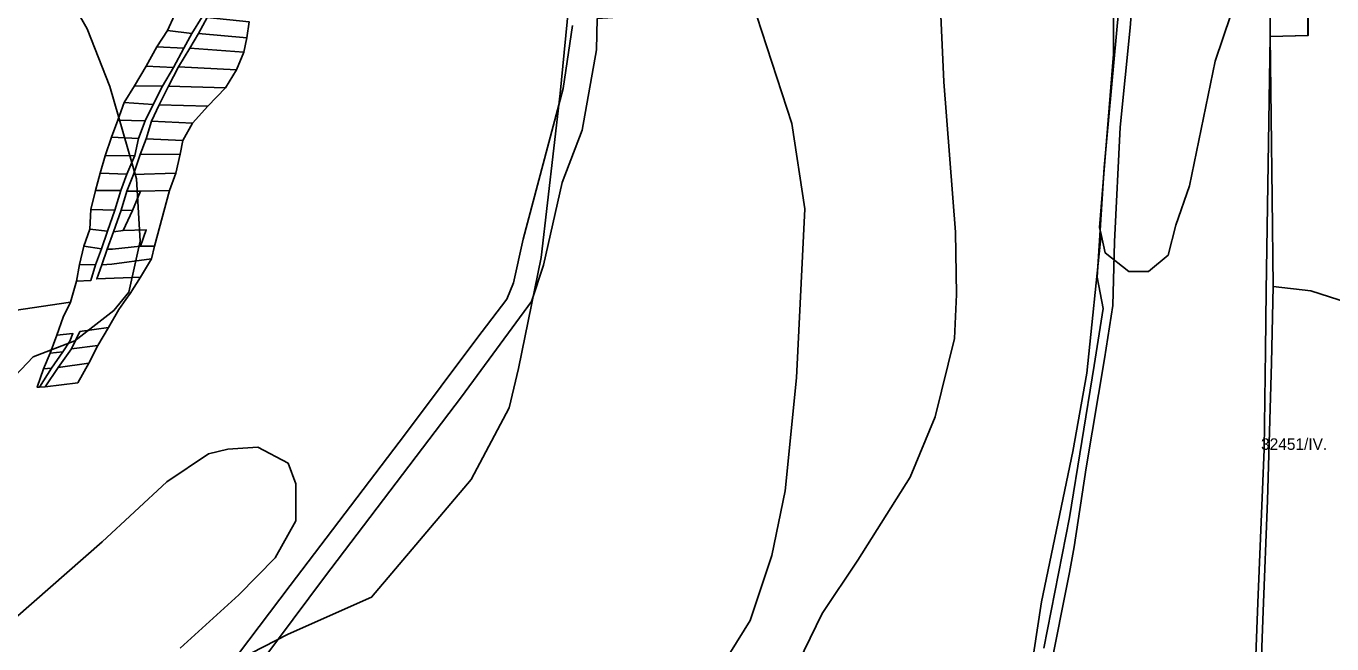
# Model space of a CAD drawing. Extents: x -532083 to -529270, y -1180561 to -1176456.
# Drawn here: x -530773 to -530208, y -1178980 to -1178713 of the extents above; entities that cross this region are included whole.
import ezdxf

# ---------------------------------------------------------------- set-up
doc = ezdxf.new("R2010")
doc.units = 0
for name, color, linetype in [('95560013', 7, 'Continuous'), ('95590013', 7, 'Continuous'), ('95600013', 7, 'Continuous'), ('95610013', 7, 'Continuous'), ('95660013', 7, 'Continuous')]:
    doc.layers.add(name, color=color, linetype=linetype)

msp = doc.modelspace()

# ---------------------------------------------------------------- linework, layer by layer
at = {"layer": '95560013'}
for points in [[(-530173.3683, -1178841.37945), (-530216.8993, -1178827.43745), (-530233.1583, -1178825.59545), (-530233.6833, -1178787.18845), (-530234.4203, -1178717.34745), (-530218.0513, -1178716.96145), (-530218.0513, -1178672.33445), (-530216.3173, -1178635.62945), (-530212.6243, -1178588.41745), (-530208.2113, -1178542.10845), (-530205.6693, -1178522.00845)], [(-530338.6833, -1179036.85645), (-530321.3203, -1178949.31245), (-530319.2753, -1178938.12245), (-530314.0693, -1178903.98945), (-530306.0673, -1178856.85845), (-530302.5943, -1178833.81345), (-530301.7933, -1178806.21445), (-530299.3893, -1178756.64145), (-530295.0563, -1178713.57145), (-530294.2473, -1178704.37145), (-530292.2243, -1178658.50245), (-530281.8383, -1178658.50245), (-530273.2063, -1178658.63745), (-530233.1463, -1178659.44945), (-530234.6123, -1178693.97245), (-530234.4203, -1178717.34745), (-530236.1723, -1178827.37845), (-530236.4583, -1178853.31145), (-530237.1233, -1178896.00145), (-530239.7833, -1178962.37045), (-530242.1383, -1179023.22645)], [(-530690.5463, -1179014.35945), (-530643.5763, -1178951.29245), (-530584.3203, -1178873.36445), (-530554.0423, -1178832.09445), (-530548.8193, -1178816.37645), (-530540.7243, -1178780.48645), (-530532.1063, -1178757.95845), (-530525.8393, -1178723.11645), (-530525.5283, -1178709.61545), (-530477.7553, -1178706.53545), (-530436.3133, -1178704.03345), (-530438.9993, -1178686.51945), (-530406.4623, -1178682.39745), (-530405.3293, -1178687.32245), (-530368.5043, -1178694.52145), (-530341.5003, -1178699.06845), (-530299.9553, -1178705.13045), (-530306.2123, -1178774.10145), (-530309.2763, -1178821.52745), (-530306.6503, -1178835.14045), (-530310.5893, -1178859.73145), (-530321.3073, -1178925.52945), (-530332.4003, -1178981.99545)], [(-530829.5283, -1178843.57645), (-530753.4283, -1178832.35745), (-530756.5093, -1178838.87745), (-530759.3103, -1178846.60445), (-530762.2283, -1178854.44745), (-530765.0293, -1178861.12145), (-530767.8303, -1178869.08245), (-530766.7803, -1178869.08245), (-530764.3293, -1178868.96545), (-530750.2063, -1178867.20945), (-530745.4213, -1178858.77945), (-530741.5703, -1178851.05245), (-530736.9013, -1178843.32545), (-530732.4663, -1178835.48145), (-530729.4203, -1178831.18945), (-530727.5643, -1178828.57445), (-530723.0553, -1178821.56445), (-530718.2813, -1178813.61845), (-530717.0633, -1178808.11745), (-530710.5633, -1178784.07545), (-530707.8203, -1178776.56845), (-530705.9153, -1178768.32545), (-530704.7243, -1178762.35245), (-530700.6753, -1178754.82645), (-530694.0053, -1178747.54045), (-530686.3833, -1178739.65545), (-530681.5013, -1178731.77145), (-530678.3583, -1178724.17245), (-530677.1223, -1178717.97145), (-530676.1083, -1178710.96645)], [(-530536.1813, -1178712.61545), (-530540.2403, -1178739.94945), (-530557.6323, -1178805.08445), (-530561.6903, -1178823.98545), (-530564.5883, -1178830.96445), (-530577.5853, -1178848.02145), (-530608.4863, -1178889.23145), (-530658.2913, -1178954.87545), (-530725.8063, -1179044.23145)]]:
    msp.add_lwpolyline(points, dxfattribs=at)
for points in [[(-530717.0633, -1178808.11745), (-530723.1563, -1178808.11745), (-530720.6173, -1178801.08845), (-530730.5703, -1178801.39345), (-530726.6093, -1178792.63345), (-530723.0553, -1178784.27945), (-530710.5633, -1178784.07545)], [(-530718.2813, -1178813.61845), (-530735.4453, -1178815.85945), (-530739.8123, -1178816.16545), (-530737.5783, -1178809.33945), (-530735.2423, -1178809.33945), (-530723.1563, -1178808.11745), (-530717.0633, -1178808.11745)], [(-530750.2063, -1178867.20945), (-530764.3293, -1178868.96545), (-530758.7273, -1178860.65245), (-530745.4213, -1178858.77945)], [(-530766.7803, -1178869.08245), (-530767.8303, -1178869.08245), (-530765.0293, -1178861.12145), (-530761.5283, -1178860.88745)]]:
    msp.add_lwpolyline(points, close=True, dxfattribs=at)
at = {"layer": '95590013'}
for points in [[(-530700.8893, -1178716.05045), (-530711.4773, -1178714.80745), (-530708.3233, -1178708.14145), (-530696.3843, -1178708.93245)], [(-530677.1223, -1178717.97145), (-530698.0733, -1178716.05045), (-530694.2433, -1178709.15845), (-530676.1083, -1178710.96645)], [(-530704.3813, -1178722.37745), (-530715.9833, -1178721.81245), (-530711.4773, -1178714.80745), (-530700.8893, -1178716.05045)], [(-530678.3583, -1178724.17245), (-530701.8203, -1178722.37545), (-530698.0733, -1178716.05045), (-530677.1223, -1178717.97145)], [(-530708.8873, -1178730.85145), (-530720.7143, -1178730.17345), (-530715.9833, -1178721.81245), (-530704.3813, -1178722.37745)], [(-530681.5013, -1178731.77145), (-530706.6293, -1178730.57645), (-530701.8203, -1178722.37545), (-530678.3583, -1178724.17245)], [(-530713.5373, -1178738.81945), (-530725.7083, -1178738.78045), (-530720.7143, -1178730.17345), (-530708.8873, -1178730.85145)], [(-530686.3833, -1178739.65545), (-530711.0363, -1178738.81945), (-530706.6293, -1178730.57645), (-530681.5013, -1178731.77145)], [(-530717.5863, -1178746.82345), (-530730.1623, -1178745.99845), (-530725.7083, -1178738.78045), (-530713.5373, -1178738.81945)], [(-530694.0053, -1178747.54045), (-530715.0853, -1178746.94245), (-530711.0363, -1178738.81945), (-530686.3833, -1178739.65545)], [(-530721.0403, -1178753.87145), (-530732.9033, -1178753.56045), (-530730.1623, -1178745.99845), (-530717.5863, -1178746.82345)], [(-530700.6753, -1178754.82645), (-530718.3003, -1178753.99045), (-530715.0853, -1178746.94245), (-530694.0053, -1178747.54045)], [(-530723.8983, -1178761.51645), (-530735.6443, -1178760.94945), (-530732.9033, -1178753.56045), (-530721.0403, -1178753.87145)], [(-530704.7243, -1178762.35245), (-530720.6823, -1178761.63645), (-530718.3003, -1178753.99045), (-530700.6753, -1178754.82645)], [(-530725.5653, -1178768.80345), (-530738.3863, -1178769.02645), (-530735.6443, -1178760.94945), (-530723.8983, -1178761.51645)], [(-530705.9153, -1178768.32545), (-530723.1833, -1178768.44545), (-530720.6823, -1178761.63645), (-530704.7243, -1178762.35245)], [(-530729.0193, -1178776.92645), (-530740.6133, -1178776.58845), (-530738.3863, -1178769.02645), (-530725.5653, -1178768.80345)], [(-530707.8203, -1178776.56845), (-530726.1613, -1178777.04645), (-530723.1833, -1178768.44545), (-530705.9153, -1178768.32545)], [(-530731.6493, -1178784.04045), (-530742.6203, -1178784.04045), (-530740.6133, -1178776.58845), (-530729.0193, -1178776.92645)], [(-530710.5633, -1178784.07545), (-530723.0553, -1178784.27945), (-530728.9453, -1178784.27945), (-530726.1613, -1178777.04645), (-530707.8203, -1178776.56845)], [(-530734.2173, -1178792.58745), (-530744.6043, -1178792.23545), (-530742.6203, -1178784.04045), (-530731.6493, -1178784.04045)], [(-530726.6093, -1178792.63345), (-530731.4843, -1178792.53145), (-530728.9453, -1178784.27945), (-530723.0553, -1178784.27945)], [(-530737.3683, -1178801.60145), (-530744.9543, -1178800.78245), (-530744.6043, -1178792.23545), (-530734.2173, -1178792.58745)], [(-530730.5703, -1178801.39345), (-530734.7343, -1178801.90345), (-530731.4843, -1178792.53145), (-530726.6093, -1178792.63345)], [(-530739.9363, -1178809.21145), (-530747.6393, -1178808.15745), (-530744.9543, -1178800.78245), (-530737.3683, -1178801.60145)], [(-530723.1563, -1178808.11745), (-530735.2423, -1178809.33945), (-530737.5783, -1178809.33945), (-530734.7343, -1178801.90345), (-530730.5703, -1178801.39345), (-530720.6173, -1178801.08845)], [(-530723.0553, -1178821.56445), (-530742.0463, -1178822.27745), (-530739.8123, -1178816.16545), (-530735.4453, -1178815.85945), (-530718.2813, -1178813.61845)], [(-530744.6043, -1178823.02645), (-530750.7903, -1178823.26045), (-530749.5063, -1178816.00145), (-530742.5033, -1178816.23545)], [(-530741.5703, -1178851.05245), (-530752.8913, -1178852.57445), (-530749.2733, -1178845.08245), (-530736.9013, -1178843.32545)], [(-530756.7423, -1178853.86245), (-530762.2283, -1178854.44745), (-530759.3103, -1178846.60445), (-530752.3073, -1178845.90145), (-530753.5913, -1178849.17945)], [(-530761.5283, -1178860.88745), (-530765.0293, -1178861.12145), (-530762.2283, -1178854.44745), (-530756.7423, -1178853.86245)], [(-530745.4213, -1178858.77945), (-530758.7273, -1178860.65245), (-530752.8913, -1178852.57445), (-530741.5703, -1178851.05245)]]:
    msp.add_lwpolyline(points, close=True, dxfattribs=at)
at = {"layer": '95600013'}
msp.add_lwpolyline([(-530230.0153, -1178613.87745), (-530228.7073, -1178598.78145), (-530227.6163, -1178583.68545), (-530226.0893, -1178568.37045), (-530224.7803, -1178553.49245), (-530223.6993, -1178540.69745), (-530208.2723, -1178542.22245), (-530212.6823, -1178588.54245), (-530216.3923, -1178635.75145), (-530218.1223, -1178672.45045), (-530218.1223, -1178716.96245), (-530234.4203, -1178717.34745), (-530234.6123, -1178693.97245), (-530233.1463, -1178659.44945), (-530232.4723, -1178643.34845), (-530231.3243, -1178628.53645)], close=True, dxfattribs=at)
at = {"layer": '95610013'}
msp.add_lwpolyline([(-530774.0523, -1178700.92945), (-530705.5063, -1178701.13745), (-530708.3233, -1178708.14145), (-530711.4773, -1178714.80745), (-530715.9833, -1178721.81245), (-530720.7143, -1178730.17345), (-530725.7083, -1178738.78045), (-530730.1623, -1178745.99845), (-530732.9033, -1178753.56045), (-530735.6443, -1178760.94945), (-530738.3863, -1178769.02645), (-530740.6133, -1178776.58845), (-530742.6203, -1178784.04045), (-530744.6043, -1178792.23545), (-530744.9543, -1178800.78245), (-530747.6393, -1178808.15745), (-530749.5063, -1178816.00145), (-530750.7903, -1178823.26045), (-530753.4283, -1178832.35745), (-530829.5283, -1178843.57645)], dxfattribs=at)
for points in [[(-530236.1723, -1178827.37845), (-530234.4203, -1178717.34745), (-530233.6833, -1178787.18845), (-530233.1583, -1178825.59545), (-530233.9753, -1178858.53445), (-530235.6433, -1178918.08545), (-530237.5493, -1178966.09445), (-530239.6343, -1179024.74345), (-530237.3683, -1179045.20245), (-530232.5843, -1179067.17745), (-530226.9003, -1179091.21545), (-530228.8463, -1179092.36745), (-530239.1813, -1179047.63845), (-530242.1383, -1179023.22645), (-530239.7833, -1178962.37045), (-530237.1233, -1178896.00145), (-530236.4583, -1178853.31145)], [(-530742.5033, -1178816.23545), (-530749.5063, -1178816.00145), (-530747.6393, -1178808.15745), (-530739.9363, -1178809.21145)], [(-530235.6433, -1178918.08545), (-530233.9753, -1178858.53445), (-530233.1583, -1178825.59545), (-530216.8993, -1178827.43745), (-530173.3683, -1178841.37945), (-530169.1723, -1178842.43145), (-530168.3143, -1178913.87145), (-530166.2283, -1178959.12945), (-530164.6633, -1178979.01145), (-530154.8043, -1179042.84745), (-530158.8983, -1179045.58545), (-530194.1503, -1179068.40045), (-530226.9003, -1179091.21545), (-530232.5843, -1179067.17745), (-530237.3683, -1179045.20245), (-530239.6343, -1179024.74345), (-530237.5493, -1178966.09445)]]:
    msp.add_lwpolyline(points, close=True, dxfattribs=at)
at = {"layer": '95660013'}
for points in [[(-530482.3753, -1179007.00045), (-530459.3753, -1178970.00045), (-530450.0003, -1178942.00045), (-530444.3123, -1178914.00045), (-530439.3753, -1178865.00045), (-530435.6873, -1178792.00045), (-530441.3753, -1178755.00045), (-530458.6253, -1178702.00045), (-530468.8753, -1178678.00045), (-530500.8753, -1178629.00045), (-530509.1253, -1178619.00045), (-530516.1253, -1178612.00045), (-530518.8753, -1178610.00045), (-530522.1873, -1178554.00045), (-530526.3123, -1178532.00045), (-530535.3123, -1178513.00045), (-530549.6253, -1178494.00045), (-530568.5003, -1178476.00045), (-530580.8123, -1178470.00045), (-530569.3753, -1178446.00045), (-530557.8753, -1178419.00045), (-530548.1253, -1178386.00045), (-530536.6873, -1178345.00045)], [(-530443.8753, -1178999.00045), (-530428.1873, -1178967.00045), (-530412.8753, -1178944.00045), (-530390.1253, -1178908.00045), (-530379.3753, -1178882.00045), (-530371.0003, -1178848.00045), (-530370.1253, -1178829.00045), (-530370.6253, -1178802.00045), (-530375.6253, -1178737.00045), (-530379.3753, -1178654.00045), (-530382.8753, -1178592.00045), (-530380.8123, -1178566.00045), (-530374.8123, -1178526.00045), (-530374.8123, -1178490.00045), (-530378.6253, -1178463.00045), (-530384.6253, -1178443.00045), (-530383.6873, -1178430.00045), (-530380.3123, -1178401.00045), (-530383.6873, -1178388.00045), (-530387.8753, -1178377.00045), (-530410.8123, -1178359.00045), (-530427.8123, -1178351.00045), (-530452.3753, -1178343.00045)], [(-530452.3753, -1178343.00045), (-530427.8123, -1178351.00045), (-530410.8123, -1178359.00045), (-530387.8753, -1178377.00045), (-530383.6873, -1178388.00045), (-530380.3123, -1178401.00045), (-530383.6873, -1178430.00045), (-530384.6253, -1178443.00045), (-530378.6253, -1178463.00045), (-530374.8123, -1178490.00045), (-530374.8123, -1178526.00045), (-530380.8123, -1178566.00045), (-530382.8753, -1178592.00045), (-530379.3753, -1178654.00045), (-530375.6253, -1178737.00045), (-530370.6253, -1178802.00045), (-530370.1253, -1178829.00045), (-530371.0003, -1178848.00045), (-530379.3753, -1178882.00045), (-530390.1253, -1178908.00045), (-530412.8753, -1178944.00045), (-530428.1873, -1178967.00045), (-530443.8753, -1178999.00045)], [(-530335.8753, -1178344.00045), (-530334.3123, -1178366.00045), (-530319.6253, -1178394.00045), (-530297.1253, -1178422.00045), (-530289.1253, -1178430.00045), (-530293.8753, -1178440.00045), (-530303.1873, -1178462.00045), (-530309.6253, -1178501.00045), (-530312.8753, -1178534.00045), (-530317.1873, -1178578.00045), (-530315.5003, -1178611.00045), (-530309.8753, -1178653.00045), (-530302.3123, -1178700.00045), (-530302.3123, -1178725.00045), (-530308.3123, -1178800.00045), (-530307.6253, -1178803.00045), (-530313.8123, -1178863.00045), (-530319.8123, -1178897.00045), (-530333.3753, -1178962.00045), (-530338.5003, -1178995.00045)], [(-530680.6253, -1178987.00045), (-530659.1873, -1178976.00045), (-530623.1253, -1178960.00045), (-530580.1253, -1178909.00045), (-530563.6873, -1178878.00045), (-530559.6253, -1178861.00045), (-530549.8123, -1178813.00045), (-530541.6253, -1178742.00045), (-530537.3753, -1178699.00045), (-530533.8123, -1178689.00045), (-530518.1873, -1178660.00045), (-530517.3753, -1178651.00045), (-530516.1253, -1178612.00045), (-530509.1253, -1178619.00045), (-530500.8753, -1178629.00045), (-530468.8753, -1178678.00045), (-530458.6253, -1178702.00045), (-530441.3753, -1178755.00045), (-530435.6873, -1178792.00045), (-530439.3753, -1178865.00045), (-530444.3123, -1178914.00045), (-530450.0003, -1178942.00045), (-530459.3753, -1178970.00045), (-530482.3753, -1179007.00045)], [(-530338.5003, -1178995.00045), (-530333.3753, -1178962.00045), (-530319.8123, -1178897.00045), (-530313.8123, -1178863.00045), (-530307.6253, -1178803.00045), (-530305.8123, -1178811.00045), (-530295.6253, -1178819.00045), (-530287.1253, -1178819.00045), (-530278.6253, -1178812.00045), (-530275.3123, -1178799.00045), (-530269.3123, -1178782.00045), (-530258.3123, -1178728.00045), (-530248.1253, -1178698.00045), (-530235.3753, -1178674.00045), (-530221.0003, -1178655.00045), (-530207.3753, -1178649.00045)], [(-530783.1873, -1178683.00045), (-530770.8753, -1178683.00045), (-530761.8753, -1178688.00045), (-530751.3753, -1178705.00045), (-530746.1253, -1178714.00045), (-530736.3123, -1178739.00045), (-530724.8123, -1178779.00045), (-530723.1873, -1178806.00045), (-530728.1253, -1178828.00045), (-530734.6873, -1178836.00045), (-530751.5003, -1178849.00045), (-530769.5003, -1178856.00045), (-530793.3123, -1178881.00045)], [(-530537.3753, -1178699.00045), (-530541.6253, -1178742.00045), (-530549.8123, -1178813.00045), (-530559.6253, -1178861.00045), (-530563.6873, -1178878.00045), (-530580.1253, -1178909.00045), (-530623.1253, -1178960.00045), (-530659.1873, -1178976.00045), (-530680.6253, -1178987.00045)], [(-530248.1253, -1178698.00045), (-530258.3123, -1178728.00045), (-530269.3123, -1178782.00045), (-530275.3123, -1178799.00045), (-530278.6253, -1178812.00045), (-530287.1253, -1178819.00045), (-530295.6253, -1178819.00045), (-530305.8123, -1178811.00045), (-530307.6253, -1178803.00045), (-530308.3123, -1178800.00045), (-530302.3123, -1178725.00045), (-530302.3123, -1178700.00045)], [(-530793.3123, -1178881.00045), (-530769.5003, -1178856.00045), (-530751.5003, -1178849.00045), (-530734.6873, -1178836.00045), (-530728.1253, -1178828.00045), (-530723.1873, -1178806.00045), (-530724.8123, -1178779.00045), (-530736.3123, -1178739.00045), (-530746.1253, -1178714.00045), (-530751.3753, -1178705.00045)], [(-530705.8753, -1178982.00045), (-530680.6253, -1178959.00045), (-530664.8753, -1178943.00045), (-530655.8753, -1178927.00045), (-530655.8753, -1178911.00045), (-530659.1873, -1178902.00045), (-530672.3123, -1178895.00045), (-530685.3753, -1178896.00045), (-530693.6873, -1178898.00045), (-530711.6873, -1178910.00045), (-530739.6253, -1178936.00045), (-530777.3123, -1178969.00045), (-530822.3753, -1179000.00045)], [(-530822.3753, -1179000.00045), (-530777.3123, -1178969.00045), (-530739.6253, -1178936.00045), (-530711.6873, -1178910.00045), (-530693.6873, -1178898.00045), (-530685.3753, -1178896.00045), (-530672.3123, -1178895.00045), (-530659.1873, -1178902.00045), (-530655.8753, -1178911.00045), (-530655.8753, -1178927.00045), (-530664.8753, -1178943.00045), (-530680.6253, -1178959.00045), (-530705.8753, -1178982.00045)]]:
    msp.add_lwpolyline(points, dxfattribs=at)

# ---------------------------------------------------------------- texts
msp.add_text('32451/IV.', height=5, rotation=0.0000001, dxfattribs=at).set_placement((-530238.4178, -1178896.24705))

doc.saveas('drawing.dxf')
